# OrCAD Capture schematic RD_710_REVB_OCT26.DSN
size B; title: RD 710
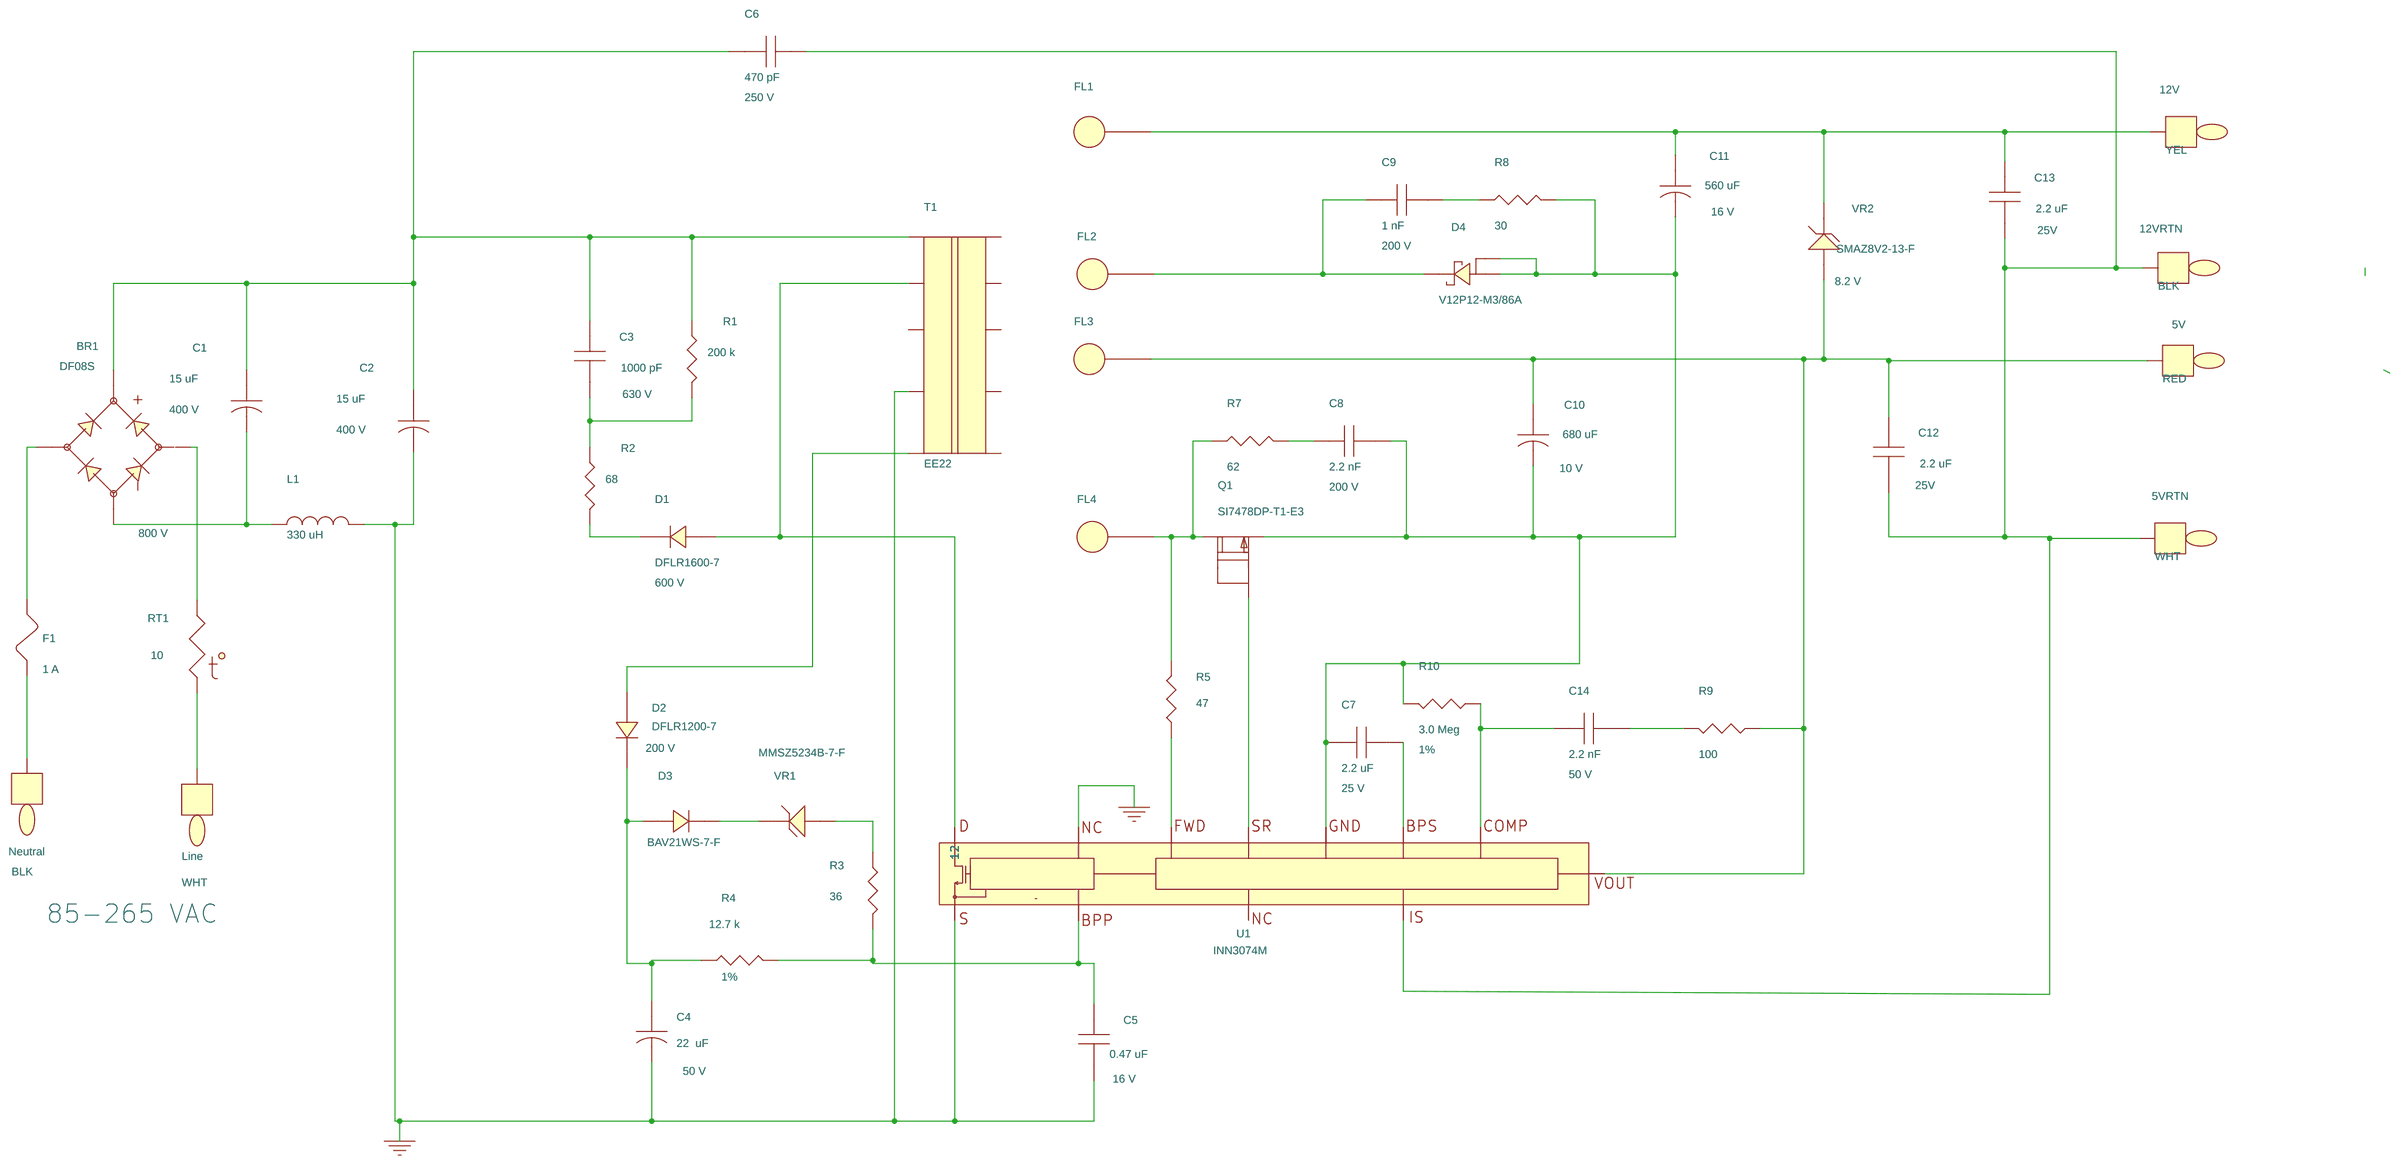
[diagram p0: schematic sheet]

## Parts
5V  RED  [pitpkeystone100x100]
5VRTN  WHT  [pitpkeystone100x100]
12V  YEL  [pitpkeystone100x100]
12VRTN  BLK  [pitpkeystone100x100]
BR1  DF08S  [pismddfs]
C1  15 uF  [pipolcapcyld400ls200040]
C2  15 uF  [pipolcapcyld400ls200040]
C3  1000 pF  [pismc1206]
C4  22  uF  [pipolcapclyd200ls80030]
C5  0.47 uF  [pismc0603]
C6  470 pF  [pinpcaprad8x5mmD030]
C7  2.2 uF  [pismc0805]
C8  2.2 nF  [pismc0805]
C9  1 nF  [pismc0805]
C10  680 uF  [pipolcapcyld400ls200040]
C11  560 uF  [pipolcapclyd320ls140030]
C12  2.2 uF  [pismc1206]
C13  2.2 uF  [pismc1206]
C14  2.2 nF  [pismc0603]
D1  DFLR1600-7  [pismddflr120012]
D2  DFLR1200-7  [pismddflr120012]
D3  BAV21WS-7-F  [pismsod323]
D4  V12P12-M3/86A  [pi_sm_d_to-277a]
F1  1 A  [pi_rst_microfuse]
FL1  Hole_30mils  [pi_hole_30mil]
FL2  Hole_30mils  [pi_hole_30mil]
FL3  Hole_30mils  [pi_hole_30mil]
FL4  Hole_30mils  [pi_hole_30mil]
L1  330 uH  [pichoketokinvd345h453ls197d030]
Line  WHT  [pitpkeystone100x100]
Neutral  BLK  [pitpkeystone100x100]
Q1  SI7478DP-T1-E3  [pismpqfn5x6b]
R1  200 k  [pismr1206]
R2  68  [pismr1206]
R3  36  [pismr0603]
R4  12.7 k  [pismr0603]
R5  47  [pismr0603]
R7  62  [pismr0805]
R8  30  [pismr0805]
R9  100  [pismr0603]
R10  3.0 Meg  [pismr0603]
RT1  10  [pi_rad_276DX197T_ls100d025]
T1  EE22  [pibobbinee22v10ptdk]
U1  INN3074M  [PI_SM_MinSOP16A_1]
VR1  MMSZ5234B-7-F  [pi_sm_sod-123_12]
VR2  SMAZ8V2-13-F  [pismdo214ac12]

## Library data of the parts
5V = TESTPOINT: Part Number: 35-00080-00
5VRTN Line = TESTPOINT: Part Number: 35-00081-00
12V = TESTPOINT: Part Number: 35-00404-00
12VRTN = TESTPOINT: Part Number: 35-00079-00
BR1 = DIODE_BRIDGE_+-~~: Disp_Voltage: 800 V; Part Number: 15-00730-00
C1 C2 = CAP_POL: ALT_SYMBOLS: pipolcapclyd400x630ls200030h; Disp_Voltage: 400 V; FPLIST: pipolcapcyld400ls200040,pipolcapclyd400x630ls200030h; Part Number: 20-08745-00; Voltage: 400 V
C3 = CAP_NP: Disp_Voltage: 630 V; Part Number: 20-08616-00; Voltage: 630 V
C4 = CAP_POL: ALT_SYMBOLS: pipolcapclyd200ls80030h; Disp_Voltage: 50 V; FPLIST: pipolcapclyd200ls80030,pipolcapclyd200ls80030h; Part Number: 20-00950-00; Voltage: 50 V
C5 = CAP_NP: Disp_Voltage: 16 V; Part Number: 20-08990-00; Voltage: 16 V
C6 = CAP_NP: Disp_Voltage: 250 V; Part Number: 20-01591-00; Voltage: 250 V
C7 = CAP_NP: Disp_Voltage: 25 V; Part Number: 20-01592-00; Voltage: 25 V
C8 = CAP_NP: Disp_Voltage: 200 V; Part Number: 20-00761-00; Voltage: 200 V
C9 = CAP_NP: Disp_Voltage: 200 V; Part Number: 20-00737-00; Voltage: 200 V
C10 = CAP_POL: ALT_SYMBOLS: pipolcapclyd400x530ls200030h; Disp_Voltage: 10 V; FPLIST: pipolcapcyld400ls200040,pipolcapclyd400x530ls200030h; Part Number: 20-00825-00; Voltage: 10 V
C11 = CAP_POL: ALT_SYMBOLS: pipolcapclyd320ls140030430h; Disp_Voltage: 16 V; FPLIST: pipolcapclyd320ls140030,pipolcapclyd320ls140030430h,pipolcapclyd320ls140030430h; Part Number: 20-09057-00; Voltage: 16 V
C12 C13 = CAP_NP: Disp_Voltage: 25V; Part Number: 20-09181-00; Voltage: 25 V
C14 = CAP_NP: Disp_Voltage: 50 V; Part Number: 20-08677-00; Voltage: 50 V
D1 = DIODE: Disp_Voltage: 600 V; Part Number: 15-00826-00
D2 = DIODE: Disp_Voltage: 200 V; Part Number: 15-01019-00
D3 = DIODE: Part Number: 15-00385-00
D4 = DIODE_SCHOTTKY_TO-277A: Part Number: 15-01194-00
F1 = FUSE: ALT_SYMBOLS: pirstmicrofusehoz; FPLIST: pi_rst_microfuse,pirstmicrofusehoz; Part Number: 40-00053-00
FL1-FL4 = FlyingLead: Part Number: 35-00284-00
L1 = INDUCTOR: Part Number: 30-00077-00
Neutral = TESTPOINT: ALT_SYMBOLS: TP_TH_CR2_D1_1; FPLIST: pitpkeystone100x100,TP_TH_CR2_D1_1; Part Number: 35-00079-00
Q1 = FET_N_SGD_123_4_5678: Part Number: 50-00147-00
R1 = R: Part Number: 05-01407-00
R2 = R: Part Number: 05-01324-00
R3 = R: Part Number: 05-01653-00
R4 = R: Disp_Tol: 1%; Part Number: 05-03192-00
R5 = R: Part Number: 05-01656-00
R7 = R: Part Number: 05-01490-00
R8 = R: Part Number: 05-01482-00
R9 = R: Part Number: 05-01664-00
R10 = R: Disp_Tol: 1%; Part Number: 05-06622-00
RT1 = THERMISTOR: Part Number: 90-00047-00
T1 = BEEL22_10P_GENERIC: Part Number: 25-00895-00
U1 = Inno3TNMinSOP16_0: Part Number: 10-01313-00
VR1 = DIODE_ZENER: Part Number: 15-01083-00
VR2 = DIODE_ZENER: Disp_Voltage: 8.2 V; Part Number: 15-01237-00

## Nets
0: C2.2 C4.2 C5.2 L1.2 T1.4 U1.9 U1.11
N11170432: BR1.1 C1.1 C2.1 C3.1 C6.2 R1.1 T1.1
N11170440: 5VRTN.1 12VRTN.1 C6.1 C12.2 C13.2 U1.1
N11170470: 12V.1 C11.1 C13.1 FL1.1 VR2.1
N11170588: C9.1 D4.3(Cathode) FL2.1
N11170596: C9.2 R8.1
N11170600: C7.1 C8.2 C10.2 C11.2 D4.1(A1) D4.2(A2) Q1.1(S) R8.2 R10.2 U1.2
N11170726: 5V.1 C10.1 C12.1 FL3.1 R9.1 U1.6 VR2.2
N11170802: D1.2 T1.2 U1.16(12)
N11170962: C3.2 R1.2 R2.1
N11171012: BR1.2 C1.2 L1.1
N11171092: BR1.4 F1.2
N11171100: BR1.3 RT1.1
N11171108: FL4.1 Q1.5(D) R5.2 R7.1
N11171116: C8.1 R7.2
N11171166: D2.2 T1.5
N11171218: D1.1 R2.2
N11171358: Q1.4(G) U1.5
N11171410: F1.1 Neutral.1
N11171438: Line.1 RT1.2
N11171478: C14.1 R10.1 U1.3
N11171534: R5.1 U1.7
N11171542: C7.2 U1.4
N11171554: C14.2 R9.2
N11171566: C4.1 D2.1 D3.2 R4.1
N11171654: D3.1 VR1.1
N11171658: R3.1 VR1.2
N11171726: C5.1 R3.2 R4.2 U1.10

Not connected (* = marked no-connect by the designer): Q1 2(S2) 3(S3) 6(D6) 7(D7) 8(D8); T1 3 6 7 8 9 10; U1 8

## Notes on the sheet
- 85-265 VAC
